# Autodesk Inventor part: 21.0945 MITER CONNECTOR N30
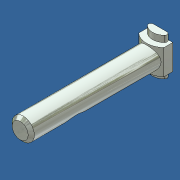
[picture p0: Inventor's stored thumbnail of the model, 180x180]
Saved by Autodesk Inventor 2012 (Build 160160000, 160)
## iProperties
Created: 2012-10
Part Number: 21.0945 MITER CONNECTOR N30
Document SubType Name: Modeling
Designer: Administrator
Density: 7.85 g/cm^3
Material: Steel
Mass: 14.6852 g
Surface Area: 12.5069 cm^2
Volume: 1.87072 cm^3
Translation Standard: STEP AP214IS
FileName: 21_0945_0_2.stp
PreProcessor: ACIS
PostProcessor: Build: 236a, Release: 2009 RTM - Date: Fri 02/22/2008
Sent Units: MM
Uncertainty: 1e-06
Author: Administrator
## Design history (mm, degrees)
feature "Base1"
body "Solid1"
